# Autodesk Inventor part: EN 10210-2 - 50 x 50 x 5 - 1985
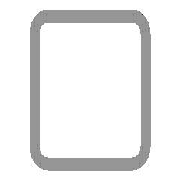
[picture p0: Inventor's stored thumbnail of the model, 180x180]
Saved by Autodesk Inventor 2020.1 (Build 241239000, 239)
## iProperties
Created: 2019-01
Part Number: EN 10210-2 - 50 x 50 x 5 - 1985
Material: Stahl, weich
Description: Rohrleitung
Document SubType Name: Modeling
Standard: DIN
Designer: lutzd
Standard Revision: 2006-07
Standards Organization: DIN
Language: de-DE
Size Designation: 50 x 50 x 5
Categories: <MemberInstance><Categories><Category DisplayName="Profile" InternalName="089c4875-fa83-4c05-b084-43b9cc11f5ed" Mnemonic="GRDR"><CategoryParameter DisplayName="
Stock Number: 50 x 50 x 5
Mass: 13603.3 g
Surface Area: 6738.18 cm^2
Volume: 1732.9 cm^3
Density: 7.85 g/cm^3
Appearance: Halbpoliert
IsCustomPart: 1
G_W: 50,000 mm
G_H: 50,000 mm
DocNumber: ADSK-014214
Folder: .
Dimensions: 50x50x1985 mm
Mass: 13,603 kg
+BFD935E9-135E-4D72-9E77-82FA049172EF+SCHNITTDETAIL1: Schnittwinkel 90,00 grd
G_L: 1985,000 mm
_CCFamilyMember: 16
_CCFamilyDisplayName: DIN EN 10210-2 (USAS B17.1 quadratisch) - Rohrleitung — In Klammern angegebene Größen wurden aufgehoben
_FrameMemberDoc: Frame Member File
_Version: 15.0.0
_GetPNFromCC: 1
Title: Profil-Bauteil
Author: lutzd
Revision Number: -
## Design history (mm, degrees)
node "Startebene"
node "Endebene"
sketch "Skizze"
  geometry: L1 (-25, -17.5)-(-25, 17.5); L2 (-17.5, 25)-(17.5, 25); L3 (25, 17.5)-(25, -17.5); L4 (17.5, -25)-(-17.5, -25); L5 (-15, 20)-(15, 20); L6 (20, 15)-(20, -15); L7 (15, -20)-(-15, -20); L8 (-20, -15)-(-20, 15); L9 (0, 37.175)-(0, -37.175) reference; L10 (-37.175, 0)-(37.175, 0) reference; A1 r 7.5 centre (-17.5, -17.5) between (-25, -17.5) and (-17.5, -25); A2 r 7.5 centre (-17.5, 17.5) between (-17.5, 25) and (-25, 17.5); A3 r 7.5 centre (17.5, 17.5) between (25, 17.5) and (17.5, 25); A4 r 7.5 centre (17.5, -17.5) between (17.5, -25) and (25, -17.5); A5 r 5 centre (-15, -15) between (-20, -15) and (-15, -20); A6 r 5 centre (-15, 15) between (-15, 20) and (-20, 15); A7 r 5 centre (15, 15) between (20, 15) and (15, 20); A8 r 5 centre (15, -15) between (15, -20) and (20, -15)
  constraints: 16 end point, 16 point on circle, 16 tangent, 8 centre point, 6 equal radius, 4 parallel, 2 perpendicular, 2 other
  dimensions: "d7" = 7.5 radius of A1 (= G_IR); "d10" = 50 distance between parallel lines of L2 L4 (= G_H); "d11" = 50 distance between parallel lines of L1 L3 (= G_W); "d12" = 5 distance between parallel lines of L3 L6 (= G_T); "d15" = 25 distance between parallel lines of L2 L10 (= 0.5 x d10); "d16" = 25 distance between parallel lines of L9 L3 (= 0.5 x d11); "d19" = 5 radius of A5 (= G_T); "d20" = 5 distance between parallel lines of L4 L7 (= G_T)
extrude "Körper" new body sketch "Skizze" stored distance "d3" = 1985 (= G_L); taper "d4" = 0 deg
node "Driven Length"
  sketch "Sketch3"
    geometry: L1 (0, 0)-(10, 0) reference
    constraints: 2 end point, 1 horizontal
  workplane "Work Plane3"
  sketch "Sketch4"
    geometry: L1 (-2, 240)-(12, 240) reference; L2 (-2, 2225)-(12, 2225) reference
    dimensions: "d18" = 1985 distance between parallel lines of L1 L2 (derived)
workplane "Arbeitsebene4"
feature "Trennen1"
sketch "Skizze5"
  geometry: L1 (1175, 0)-(1175, 35) reference; L2 (1175, 17.5)-(939, 17.5); 3 further points
  constraints: 4 end point, 1 coincident, 1 horizontal, 1 midpoint, 1 point on line, 1 vertical, 2 other
  dimensions: "d21" = 64 distance of point (1003, 17.5) point (939, 17.5); "d22" = 172 distance from line of L1 point (1003, 17.5)
hole "Bohrung1" sketch "Skizze5" at (939, 17.5), (1003, 17.5) diameter "d23" = 6.647; stored, may be unused: countersink angle "d27" = 90 deg, drill point angle "d29" = 118 deg; dims "d24" = 16, "d25" = 4, "d26" = 2, "d28" = 8
body "Solid1"
other parameters: "G_W" = 50 [user parameter; used in 1 equation term], "G_H" = 50 [user parameter; used in 1 equation term], "G_T" = 5 [user parameter; used in 3 equation terms], "G_IR" = 7.5 [user parameter; used in 1 equation term], "G_L" = 1985 (= d18) [user parameter; used in 1 equation term], "G_OFFSET_END" = 0 [user parameter; used in 1 equation term], "d14" = 2225 (= G_OFFSET_END + B_L), "B_L" = 2225 [user parameter; used in 1 equation term], "d17" = 90 deg
